// Mitsubishi GX Works2 project: BD4543通信ADPRW_CH2   PLC: FX3U/FX3UC

PROGRAM MAIN
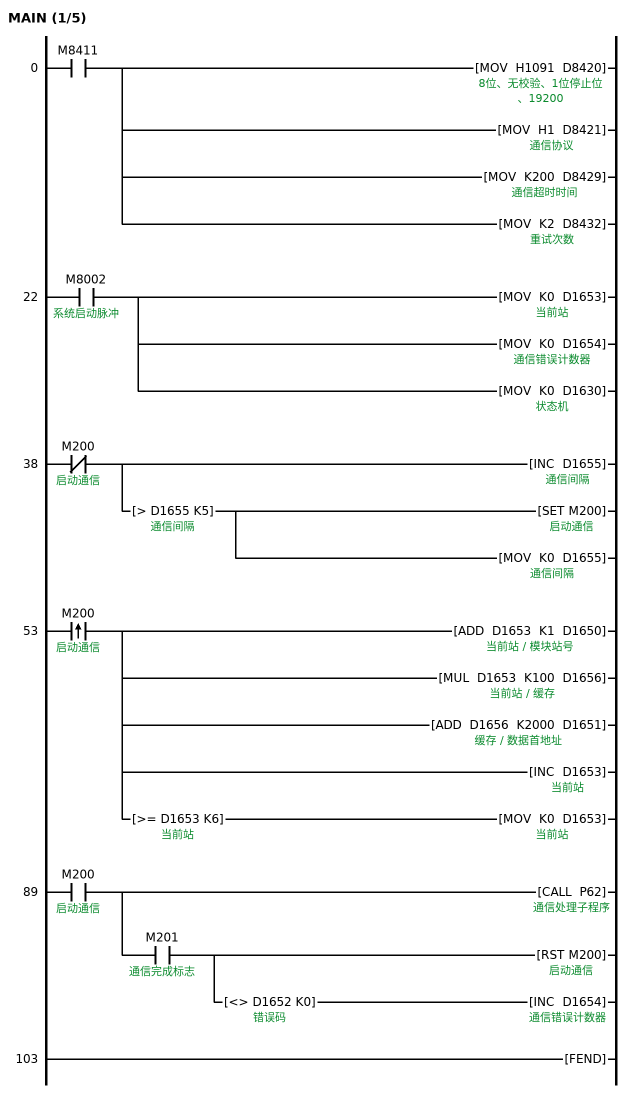
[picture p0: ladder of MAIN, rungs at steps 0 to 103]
0     LD      M8411
      MOV     H1091 D8420  ; 8位、无校验、1位停止位、19200
      MOV     H1 D8421  ; 通信协议
      MOV     K200 D8429  ; 通信超时时间
      MOV     K2 D8432  ; 重试次数
22    LD      M8002  ; 系统启动脉冲
      MOV     K0 D1653  ; 当前站
      MOV     K0 D1654  ; 通信错误计数器
      MOV     K0 D1630  ; 状态机
38    LDI     M200  ; 启动通信
      INC     D1655  ; 通信间隔
      AND>    D1655 K5  ; 通信间隔
      SET     M200  ; 启动通信
      MOV     K0 D1655
53    LDP     M200  ; 启动通信
      ADD     D1653 K1 D1650  ; 模块站号
      MUL     D1653 K100 D1656  ; 缓存
      ADD     D1656 K2000 D1651  ; 数据首地址
      INC     D1653
      AND>=   D1653 K6  ; 当前站
      MOV     K0 D1653
89    LD      M200  ; 启动通信
      CALL    P62  ; 通信处理子程序
      AND     M201  ; 通信完成标志
      RST     M200  ; 启动通信
      AND<>   D1652 K0  ; 错误码
      INC     D1654
103   FEND
; BD4543通信处理子程序
; 输入参数：D1650 模块站号
; D1651 数据起始地址
; 输出参数：M201 工作状态：1完成、0忙
      P62
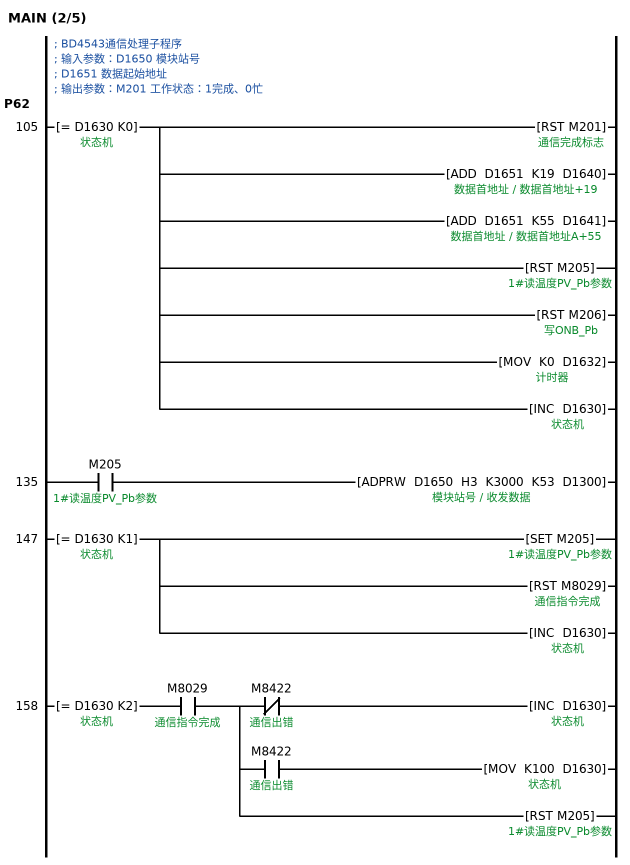
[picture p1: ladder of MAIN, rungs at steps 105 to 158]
105   LD=     D1630 K0  ; 状态机
      RST     M201  ; 通信完成标志
      ADD     D1651 K19 D1640  ; 数据首地址+19
      ADD     D1651 K55 D1641  ; 数据首地址A+55
      RST     M205  ; 1#读温度PV_Pb参数
      RST     M206  ; 写ONB_Pb
      MOV     K0 D1632  ; 计时器
      INC     D1630
135   LD      M205  ; 1#读温度PV_Pb参数
      ADPRW   D1650 H3 K3000 K53 D1300  ; 收发数据
147   LD=     D1630 K1  ; 状态机
      SET     M205  ; 1#读温度PV_Pb参数
      RST     M8029  ; 通信指令完成
      INC     D1630
158   LD=     D1630 K2  ; 状态机
      AND     M8029  ; 通信指令完成
      MPS
      ANI     M8422  ; 通信出错
      INC     D1630
      MRD
      AND     M8422  ; 通信出错
      MOV     K100 D1630
      MPP
      RST     M205  ; 1#读温度PV_Pb参数
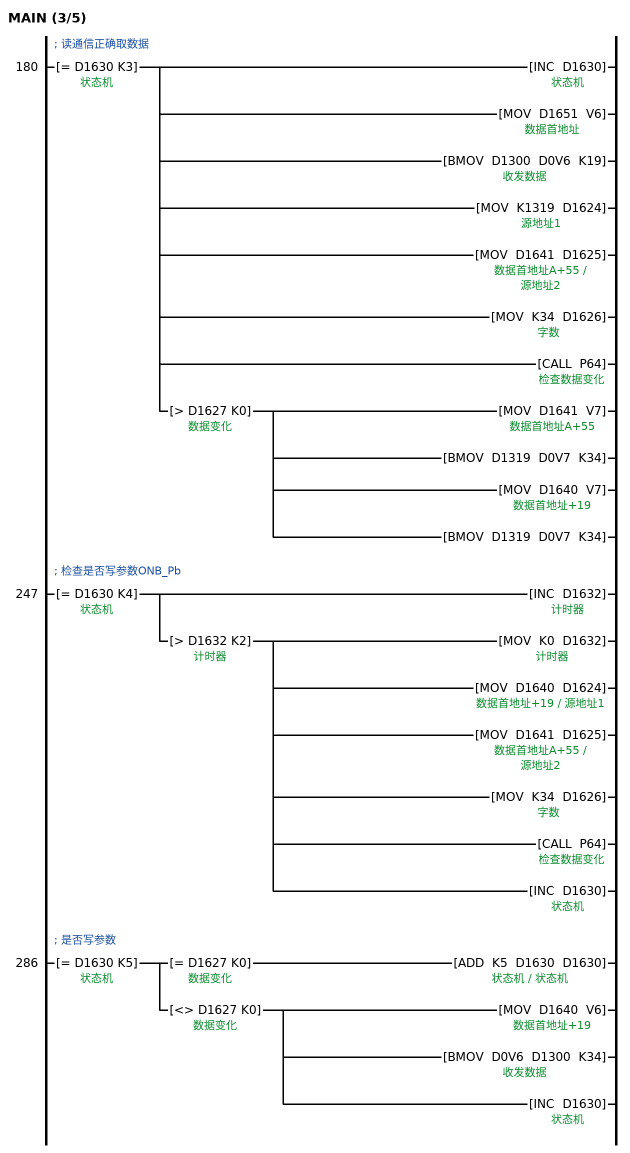
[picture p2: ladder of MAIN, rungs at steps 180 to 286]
; 读通信正确取数据
180   LD=     D1630 K3  ; 状态机
      INC     D1630
      MOV     D1651 V6
      BMOV    D1300 D0V6 K19
      MOV     K1319 D1624  ; 源地址1
      MOV     D1641 D1625  ; 源地址2
      MOV     K34 D1626  ; 字数
      CALL    P64  ; 检查数据变化
      AND>    D1627 K0  ; 数据变化
      MOV     D1641 V7
      BMOV    D1319 D0V7 K34
      MOV     D1640 V7
      BMOV    D1319 D0V7 K34
; 检查是否写参数ONB_Pb
247   LD=     D1630 K4  ; 状态机
      INC     D1632
      AND>    D1632 K2  ; 计时器
      MOV     K0 D1632
      MOV     D1640 D1624
      MOV     D1641 D1625
      MOV     K34 D1626
      CALL    P64
      INC     D1630
; 是否写参数
286   LD=     D1630 K5  ; 状态机
      MPS
      AND=    D1627 K0  ; 数据变化
      ADD     K5 D1630 D1630
      MPP
      AND<>   D1627 K0  ; 数据变化
      MOV     D1640 V6
      BMOV    D0V6 D1300 K34
      INC     D1630
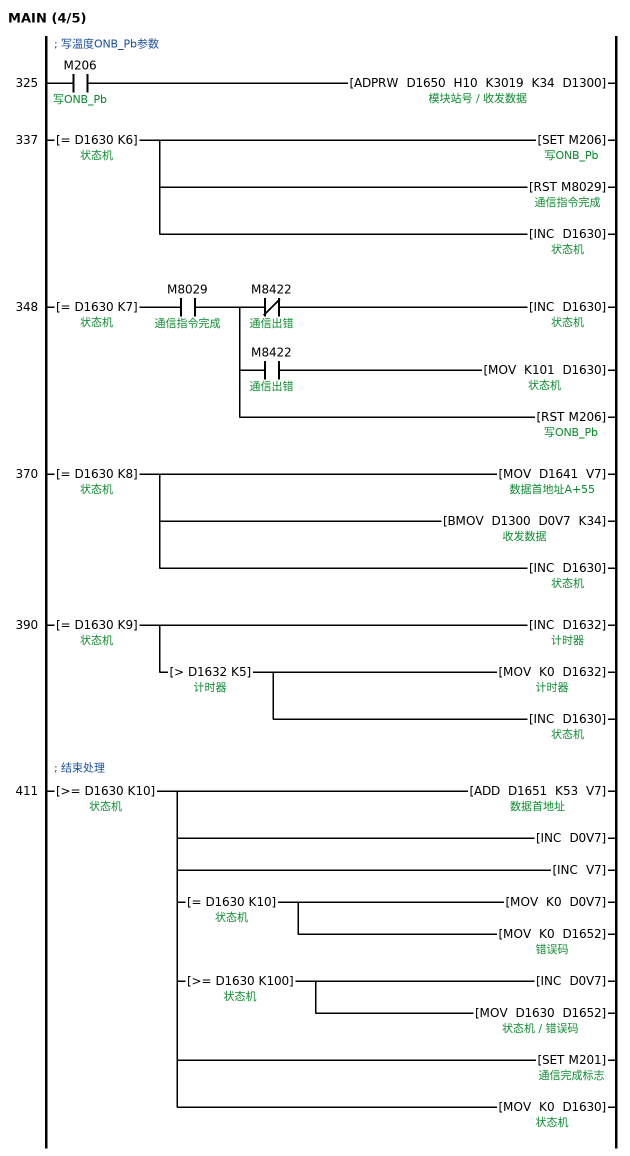
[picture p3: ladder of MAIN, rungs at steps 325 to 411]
; 写温度ONB_Pb参数
325   LD      M206  ; 写ONB_Pb
      ADPRW   D1650 H10 K3019 K34 D1300
337   LD=     D1630 K6  ; 状态机
      SET     M206  ; 写ONB_Pb
      RST     M8029  ; 通信指令完成
      INC     D1630
348   LD=     D1630 K7  ; 状态机
      AND     M8029  ; 通信指令完成
      MPS
      ANI     M8422  ; 通信出错
      INC     D1630
      MRD
      AND     M8422  ; 通信出错
      MOV     K101 D1630
      MPP
      RST     M206  ; 写ONB_Pb
370   LD=     D1630 K8  ; 状态机
      MOV     D1641 V7
      BMOV    D1300 D0V7 K34
      INC     D1630
390   LD=     D1630 K9  ; 状态机
      INC     D1632
      AND>    D1632 K5  ; 计时器
      MOV     K0 D1632
      INC     D1630
; 结束处理
411   LD>=    D1630 K10  ; 状态机
      ADD     D1651 K53 V7
      INC     D0V7
      INC     V7
      MPS
      AND=    D1630 K10  ; 状态机
      MOV     K0 D0V7
      MOV     K0 D1652
      MRD
      AND>=   D1630 K100  ; 状态机
      INC     D0V7
      MOV     D1630 D1652
      MPP
      SET     M201  ; 通信完成标志
      MOV     K0 D1630
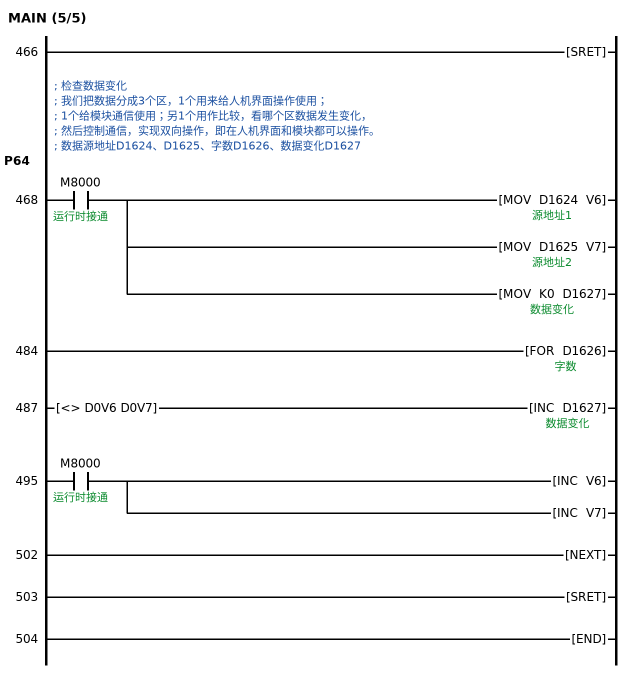
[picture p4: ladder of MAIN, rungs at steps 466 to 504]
466   SRET
; 检查数据变化
; 我们把数据分成3个区，1个用来给人机界面操作使用；
; 1个给模块通信使用；另1个用作比较，看哪个区数据发生变化，
; 然后控制通信，实现双向操作，即在人机界面和模块都可以操作。
; 数据源地址D1624、D1625、字数D1626、数据变化D1627
; 
      P64
468   LD      M8000  ; 运行时接通
      MOV     D1624 V6
      MOV     D1625 V7
      MOV     K0 D1627
484   FOR     D1626
487   LD<>    D0V6 D0V7
      INC     D1627
495   LD      M8000  ; 运行时接通
      INC     V6
      INC     V7
502   NEXT
503   SRET
504   END
END_PROGRAM

// device comments not shown above
M202  ; >
M203  ; =
M204  ; <
D101  ; 需要校验的数据的起始地址
D102  ; CRC高字节
D103  ; CRC低字节
D110  ; 当前模块站号
D151  ; 功能码
D152  ; 起始地址高字节
D153  ; 起始地址低字节
D154  ; 数据通道数高字节
D155  ; 数据通道数低字节
D1000  ; 发字节
D1002  ; 功能码
D1003  ; 开始地址高位
D1004  ; 开始地址低位
D1005  ; 数据高位
D1006  ; 数据低位
D1007  ; 字节数
D1301  ; 收地址
D1400  ; 写参数缓存
D1600  ; 转换源地址
D1601  ; 目的地址
D1602  ; 字数
D1605  ; 源地址
D1606  ; 目地址
D1607  ; 字数
D1615  ; 参数地址
D1617  ; 参数地址
D1619  ; 通道号
D1620  ; 命令码
D1621  ; 缓存
D1631  ; 时间标记
D1634  ; 需要校验的字节数
D1635  ; 需要校验的数据首地址
D1636  ; CRC高字节
D1637  ; CRC低字节
D1657  ; 缓存
D1660  ; 启动关闭整定标记
D1661  ; 通道0~7
D1662  ; 查通道
D1663  ; 要发送整定参数
D1664  ; 启动/关闭整定
D1665  ; 整定状态
T240  ; 系统启动延时
T241  ; 通信间隔时间
T242  ; 通信故障重启动时间
P60  ; CRC校验子程序P60
P61  ; 通信初始化
P65  ; 读温度及常用参数准备
P66  ; 字转为字节
P67  ; 字节转换为字
P68  ; 读手动、输出、输出限位值初始化
P69  ; 写给定温度、常用参数准备
P70  ; 写手动输出、输出限位准备
P71  ; 自整定数据准备
